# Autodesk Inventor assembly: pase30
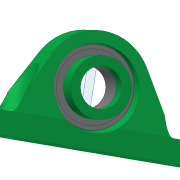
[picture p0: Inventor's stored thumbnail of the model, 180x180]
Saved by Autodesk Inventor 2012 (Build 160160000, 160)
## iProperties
Company: CAD-Verlag
Shininess: 64.0
Length Units: 11269
Angle Units: 11279
Time Units: 11290
Mass Units: 11283
Length Display Precision: 3
Angle Display Precision: 2
Compacted: True
Created: 2004-09
Part Number: pase30
Document SubType Name: Assembly
Designer: Greiling
Manufacturer: Standard
Standards Organization: Custom
Control State: 0
Master: False
Checked Out: False
Density: 0.0
Volumn: 0.0
Area: 0.0
PropertySet Name: Model Information
Author: Jürgen Kronas
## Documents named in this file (12)
- C:\DemoDaten2012\CAD Daten\Daten Vault 2012 Inventor\Kapitel 6\6.4\Rollenbahn\Rollenbahn 1400\pase30.iam
- C:\DemoDaten2012\CAD Daten\Daten Vault 2012 Inventor\Kapitel 6\6.4\Rollenbahn\Rollenbahn 1400\x_1.ipt
- C:\DemoDaten2012\CAD Daten\Daten Vault 2012 Inventor\Kapitel 6\6.4\Rollenbahn\Rollenbahn 1400\x_2.ipt
- C:\DemoDaten2012\CAD Daten\Daten Vault 2012 Inventor\Kapitel 6\6.4\Rollenbahn\Rollenbahn 1400\x_3.ipt
- C:\DemoDaten2012\CAD Daten\Daten Vault 2012 Inventor\Kapitel 6\6.4\Rollenbahn\Rollenbahn 1400\x_4.ipt
- C:\DemoDaten2012\CAD Daten\Daten Vault 2012 Inventor\Kapitel 6\6.4\Rollenbahn\Rollenbahn 1400\x_5.ipt
- C:\DemoDaten2012\CAD Daten\Daten Vault 2012 Inventor\Kapitel 6\6.4\Rollenbahn\Rollenbahn 1400\x_6.ipt
- C:\DemoDaten2012\CAD Daten\Daten Vault 2012 Inventor\Kapitel 6\6.4\Rollenbahn\Rollenbahn 1400\x_7.ipt
- C:\DemoDaten2012\CAD Daten\Daten Vault 2012 Inventor\Kapitel 6\6.4\Rollenbahn\Rollenbahn 1400\x_8.ipt
- C:\DemoDaten2012\CAD Daten\Daten Vault 2012 Inventor\Kapitel 6\6.4\Rollenbahn\Rollenbahn 1400\x_9.ipt
- C:\DemoDaten2012\CAD Daten\Daten Vault 2012 Inventor\Kapitel 6\6.4\Rollenbahn\Rollenbahn 1400\x_10.ipt
- C:\DemoDaten2012\CAD Daten\Daten Vault 2012 Inventor\Kapitel 6\6.4\Rollenbahn\Rollenbahn 1400\x_11.ipt
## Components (11 placed, 11 different names)
1. x_1:1
2. x_2:1
3. x_3:1
4. x_4:1
5. x_5:1
6. x_6:1
7. x_7:1
8. x_8:1
9. x_9:1
10. x_10:1
11. x_11:1
